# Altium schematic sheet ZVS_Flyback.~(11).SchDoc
size 431 x 279 mm; Date: Not shown in title block; ApprovedBy: Not shown in title block; CheckedBy: Not shown in title block; Author: Not shown in title block; CompanyName: Not shown in title block; Engineer: Not shown in title block; Organization: Not shown in title block; Address1: Not shown in title block; Address2: Not shown in title block; Address3: Not shown in title block; Address4: Not shown in title block; DocumentNumber: 2; Revision: Use project parameter SCH_Rev; SheetNumber: 2; SheetTotal: 2; PageSetup: Record=PageOptions¦CenterHorizontal=True¦CenterVertical=True¦PrintScale=1.00¦XCorrection=1.00¦YCorrection=1.00¦PrintKind=0¦BorderSize=5000000¦LeftOffset=0¦BottomOffset=0¦Orientation=2¦PaperLength=1000¦PaperWidth=1000¦Scale=100¦PaperSource=15¦PrintQuality=600¦MediaType=1¦DitherType=10¦PaperKind=Letter¦PrintScaleMode=1
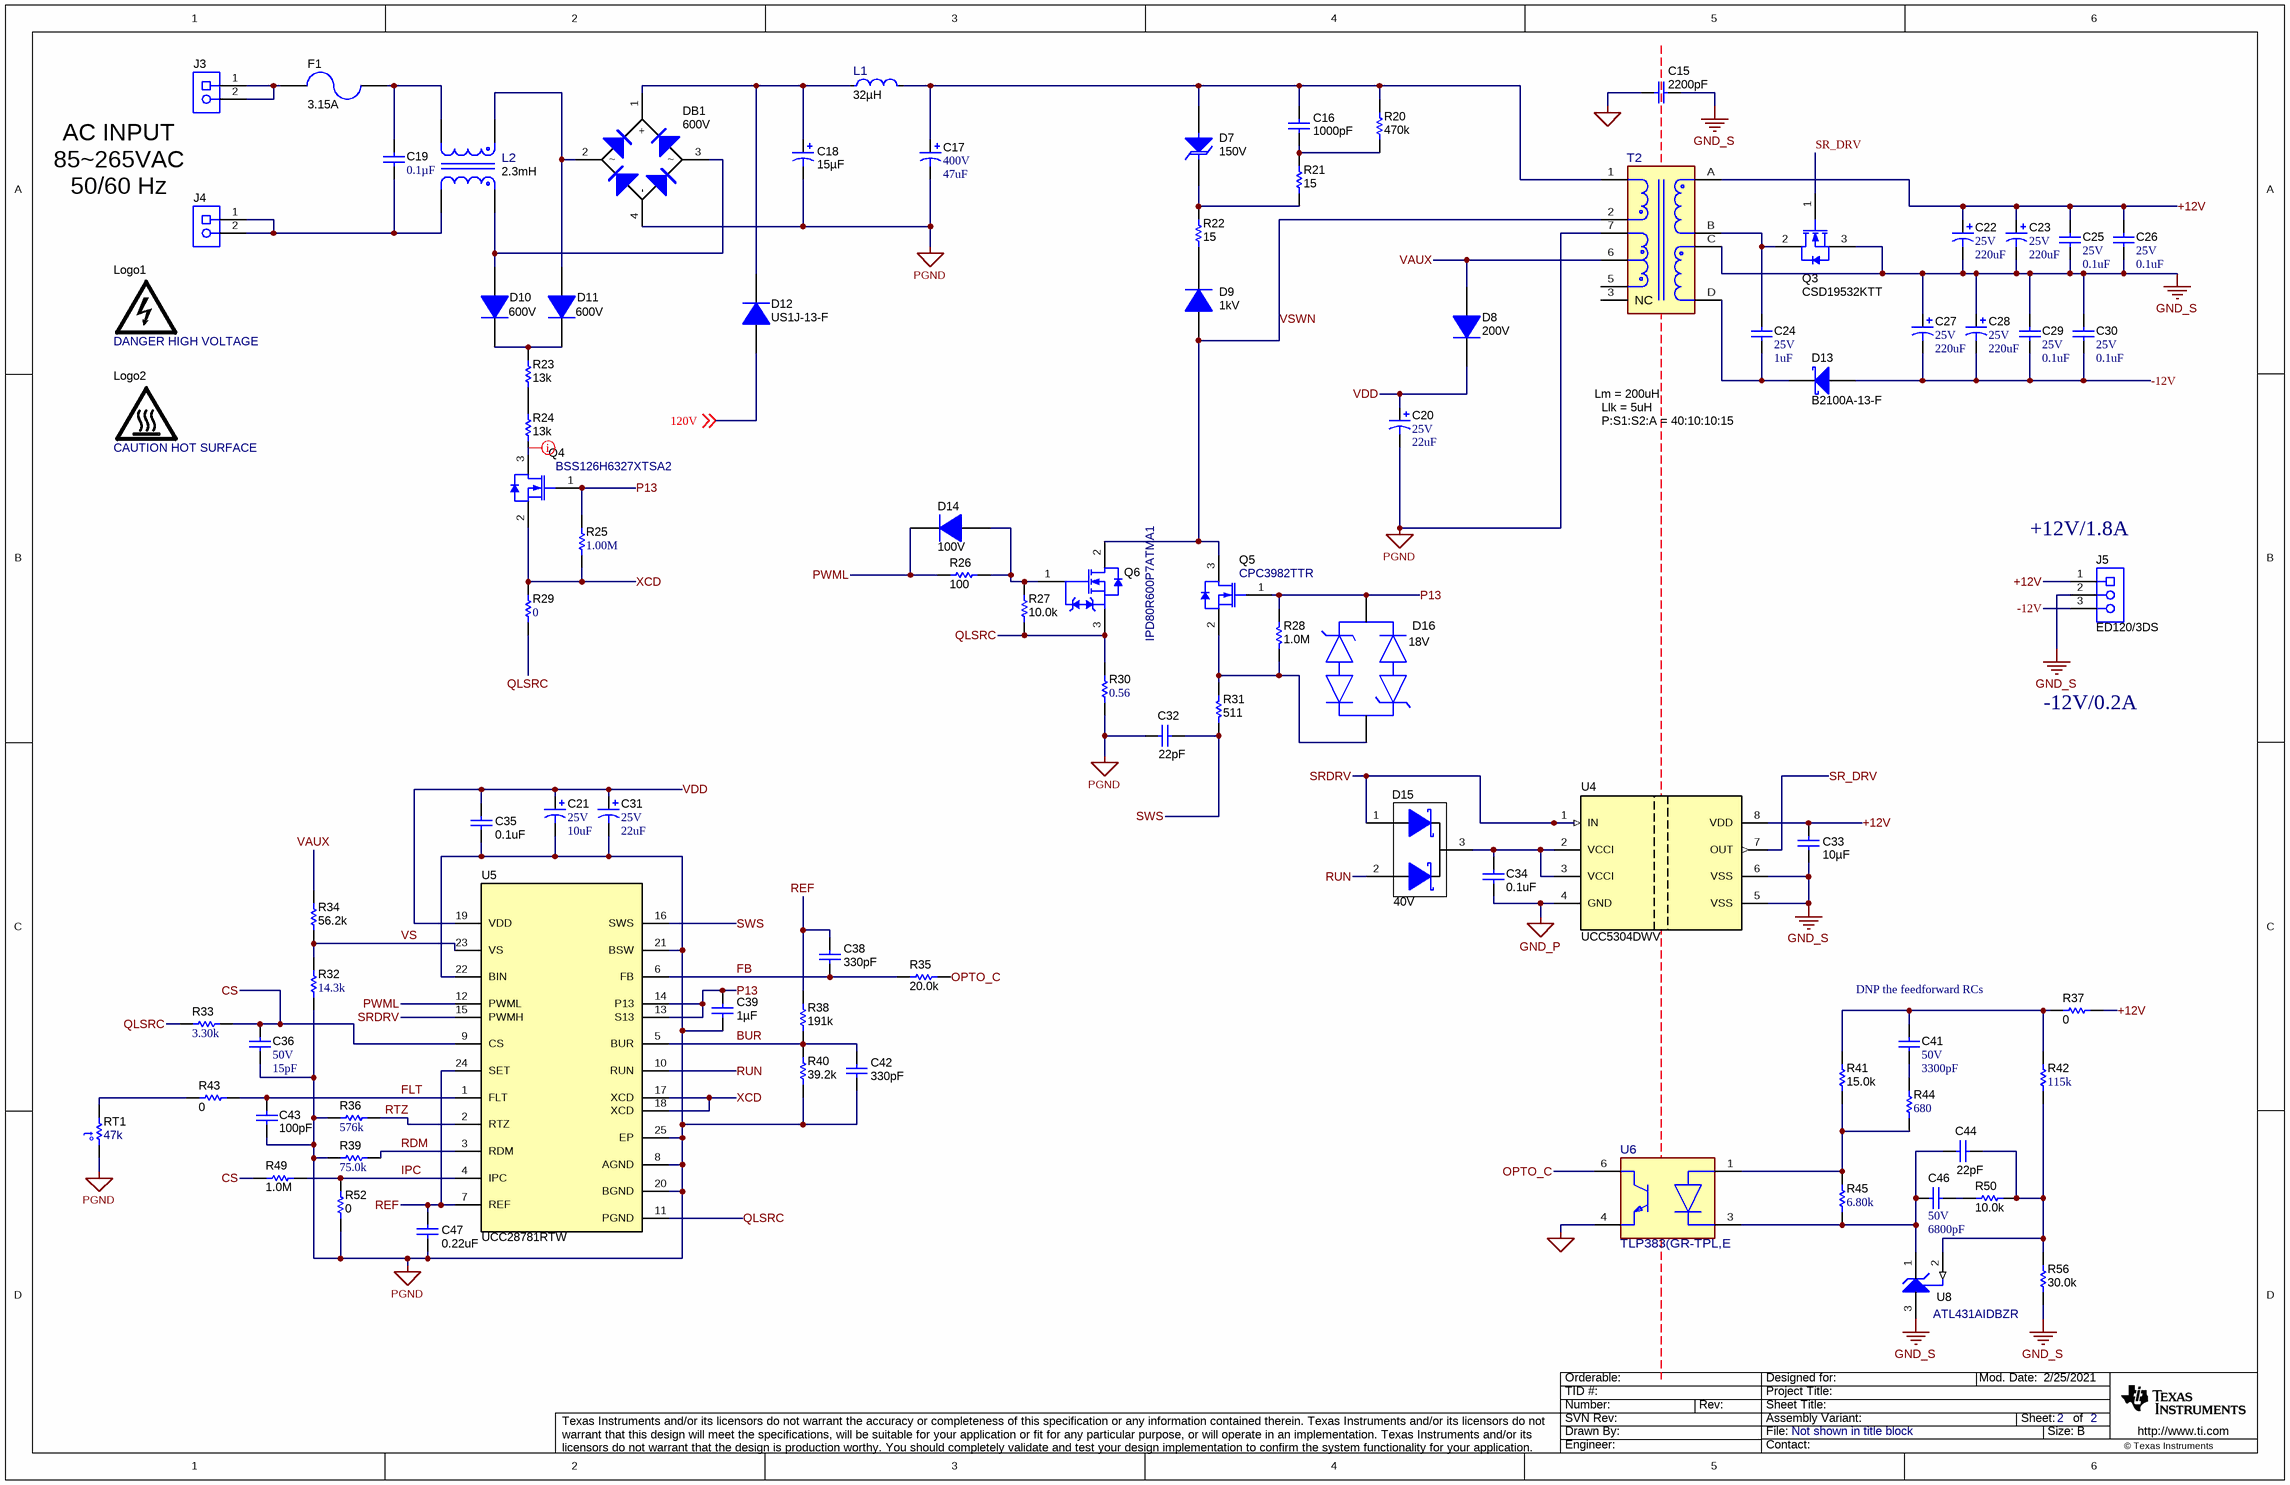
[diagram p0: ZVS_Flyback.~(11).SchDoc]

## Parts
C15  ValueDisplayed: 2200pF  [C900_9x13]  (hidden comment: C921U222MVVDBA7317)
C16  ValueDisplayed: 1000pF  [1206L]  (hidden comment: GRM31BR72J102KW01L)
C17  VDC_V: 400V  ValueDisplayed: 47uF  [CAPPR7.5-16x25]  (hidden comment: UCS2G470MHD)
C18  ValueDisplayed: 15µF  [UVC_1000x1600]  (hidden comment: UVC2G150MPD)
C19  ValueDisplayed: 0.1µF  [B32933_600x1500x2650]  (hidden comment: B32933A3104K000)
C20  VDC_V: 25V  ValueDisplayed: 22uF  [SM_RADIAL_D]  (hidden comment: EEE-FC1E220P)
C21  VDC_V: 25V  ValueDisplayed: 10uF  [CAPSMT_62_D55]  (hidden comment: EMVA250ADA100MD55G)
C22  VDC_V: 25V  ValueDisplayed: 220uF  [BT_1000x1250]  (hidden comment: UBT1E221MPD1TD)
C23  VDC_V: 25V  ValueDisplayed: 220uF  [BT_1000x1250]  (hidden comment: UBT1E221MPD1TD)
C24  VDC_V: 25V  ValueDisplayed: 1uF  [1206]  (hidden comment: GRM319R61E105KC36D)
C25  VDC_V: 25V  ValueDisplayed: 0.1uF  [0603]  (hidden comment: 06033D104KAT2A)
C26  VDC_V: 25V  ValueDisplayed: 0.1uF  [0603]  (hidden comment: 06033D104KAT2A)
C27  VDC_V: 25V  ValueDisplayed: 220uF  [BT_1000x1250]  (hidden comment: UBT1E221MPD1TD)
C28  VDC_V: 25V  ValueDisplayed: 220uF  [BT_1000x1250]  (hidden comment: UBT1E221MPD1TD)
C29  VDC_V: 25V  ValueDisplayed: 0.1uF  [0603]  (hidden comment: 06033D104KAT2A)
C30  VDC_V: 25V  ValueDisplayed: 0.1uF  [0603]  (hidden comment: 06033D104KAT2A)
C31  VDC_V: 25V  ValueDisplayed: 22uF  [SM_RADIAL_D]  (hidden comment: EEE-FC1E220P)
C32  ValueDisplayed: 22pF  [0402S]  (hidden comment: GCM1555C1H220JA16D)
C33  ValueDisplayed: 10µF  [1206_180L]  (hidden comment: C1206C106J3RACAUTO)
C34  ValueDisplayed: 0.1uF  [0402S]  (hidden comment: GRM155R71H104ME14D)
C35  ValueDisplayed: 0.1uF  [0402S]  (hidden comment: GRM155R71H104ME14D)
C36  VDC_V: 50V  ValueDisplayed: 15pF  [0402]  (hidden comment: CC0402JRNPO9BN150)
C38  ValueDisplayed: 330pF  [0402S]  (hidden comment: GRM155R71H331KA01D)
C39  Cap_F: 1µF  [0603S]  (hidden comment: CGA3E1X7R1V105K080AC)
C41  VDC_V: 50V  ValueDisplayed: 3300pF  [0402]  (hidden comment: GRM155R71H332KA01D)
C42  ValueDisplayed: 330pF  [0402S]  (hidden comment: GRM155R71H331KA01D)
C43  ValueDisplayed: 100pF  [0402S]  (hidden comment: GRM1555C1H101JA01D)
C44  ValueDisplayed: 22pF  [0402S]  (hidden comment: GCM1555C1H220JA16D)
C46  VDC_V: 50V  ValueDisplayed: 6800pF  [0402]  (hidden comment: GRM155R71H682KA88D)
C47  ValueDisplayed: 0.22uF  [0402S]  (hidden comment: GRM155R71C224KA12D)
D7  VRWM: 150V  [SMA]  (hidden comment: SMAJ150A)
D8  Vr_V: 200V  [SOD-123H]  (hidden comment: CSFMT104-HF)
D9  Vr_V: 1kV  [SMA]  (hidden comment: MRA4007T3G)
D10  Vr_V: 600V  [TUMD2SM]  (hidden comment: RFU02VSM6STR)
D11  Vr_V: 600V  [TUMD2SM]  (hidden comment: RFU02VSM6STR)
D12  US1J-13-F  [SMA]
D13  B2100A-13-F  [SMA]
D14  Vr_V: 100V  [SOD-323]  (hidden comment: BAS316,115)
D15  Vr_V: 40V  [SOT-323]  (hidden comment: BAS40W-05-7-F)
D16  CDSOD323-T18C  [FP-CDSOD323-T18C_SOD323-MFG]  (value not drawn)
DB1  value 600V  [Z4-D]  (hidden comment: Z4DGP406L-HF)
F1  Irating_A: 3.15A  [FUSE_392]  (hidden comment: 39213150000)
J3  ED120/2DS  [On-Shore_ED120_2DS]  (value not drawn)
J4  ED120/2DS  [On-Shore_ED120_2DS]  (value not drawn)
J5  ED120/3DS  [On-Shore_ED120_3DS]
L1  Ind_H: 32µH  [FP-7447052_PTH_D10MM0-MFG]  (hidden comment: 7447052)
L2  Ind_H: 2.3mH  [FP-RLTI-1387_PTH_CMC_0IN38_0IN60-MFG]  (hidden comment: RLTI-1387)
Logo1  DANGER HIGH VOLTAGE  [IEC_HighVoltage_Small]  (no BOM)
Logo2  CAUTION HOT SURFACE  [IEC_HotSurface_Small]  (no BOM)
Q3  CSD19532KTT  [KTT0002A]
Q4  BSS126H6327XTSA2  [SOT-23L]
Q5  CPC3982TTR  [SOT-23L]
Q6  IPD80R600P7ATMA1  [DPAK]
R20  ValueDisplayed: 470k  [0805_HV1]  (hidden comment: CRCW0805470KJNEA)
R21  ValueDisplayed: 15  [0805_HV1]  (hidden comment: CRCW080515R0JNEA)
R22  ValueDisplayed: 15  [0805_HV1]  (hidden comment: CRCW080515R0JNEA)
R23  ValueDisplayed: 13k  [1206L]  (hidden comment: CRCW120613K0JNEA)
R24  ValueDisplayed: 13k  [1206L]  (hidden comment: CRCW120613K0JNEA)
R25  ValueDisplayed: 1.00M  [0603]  (hidden comment: MCT06030C1004FP500)
R26  ValueDisplayed: 100  [0805_HV1]  (hidden comment: CRCW0805100RJNEA)
R27  ValueDisplayed: 10.0k  [0402S]  (hidden comment: CRCW040210K0FKED)
R28  ValueDisplayed: 1.0M  [0402S]  (hidden comment: CRCW04021M00JNED)
R29  ValueDisplayed: 0  [0603]  (hidden comment: RC0603JR-070RL)
R30  ValueDisplayed: 0.56  [1206]  (hidden comment: ERJ-8RQFR56V)
R31  ValueDisplayed: 511  [0402S]  (hidden comment: CRCW0402511RFKED)
R32  ValueDisplayed: 14.3k  [0402]  (hidden comment: CRCW040214K3FKED)
R33  ValueDisplayed: 3.30k  [0402]  (hidden comment: RK73H1ETTP3301F)
R34  ValueDisplayed: 56.2k  [0402S]  (hidden comment: CRCW040256K2FKED)
R35  ValueDisplayed: 20.0k  [0402S]  (hidden comment: CRCW040220K0FKED)
R36  ValueDisplayed: 576k  [0402]  (hidden comment: CRCW0402576KFKED)
R37  ValueDisplayed: 0  [0402S]  (hidden comment: RC0402JR-070RL)
R38  ValueDisplayed: 191k  [0402S]  (hidden comment: CRCW0402191KFKED)
R39  ValueDisplayed: 75.0k  [0402]  (hidden comment: CRCW040275K0FKED)
R40  ValueDisplayed: 39.2k  [0402S]  (hidden comment: CRCW040239K2FKED)
R41  ValueDisplayed: 15.0k  [0402S]  (hidden comment: CRCW040215K0FKED)
R42  ValueDisplayed: 115k  [0402]  (hidden comment: RC1005F1153CS)
R43  ValueDisplayed: 0  [0402S]  (hidden comment: CRCW04020000Z0EDHP)
R44  ValueDisplayed: 680  [0603]  (hidden comment: RC0603FR-07680RL)
R45  ValueDisplayed: 6.80k  [0603]  (hidden comment: RC0603FR-076K8L)
R49  ValueDisplayed: 1.0M  [0402S]  (hidden comment: CRCW04021M00JNED)
R50  ValueDisplayed: 10.0k  [0402S]  (hidden comment: CRCW040210K0FKED)
R52  ValueDisplayed: 0  [0402S]  (hidden comment: CRCW04020000Z0EDHP)
R56  ValueDisplayed: 30.0k  [0402S]  (hidden comment: CRCW040230K0FKED)
RT1  value 47k  [0603S]  (hidden comment: NCP18WB473J03RB)
T2  RLTI-1324  [FP-RLTI-1324_PTH_0IN980_0IN766-MFG]  (value not drawn)
U4  UCC5304DWV  [DWV0008A]
U5  UCC28781RTW  [RTW0024B]
U6  TLP383(GR-TPL,E  [FP-TLP383(GR-TPL,E_SO6-4-MFG]
U8  ATL431AIDBZR  [DBZ0003A_L]

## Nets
GND2: C15.2 U6.4(Emitter)
GND_P: C34.2 U4.4(GND)
GND_S: C15.1 C22.2(-) C23.2(-) C25.2 C26.2 C27.1(+) C28.1(+) C29.1 C30.1 C33.2 J5.2 Q3.3(S) R56.2 T2.C U4.5(VSS) U4.6(VSS) U8.3(ANODE)
PGND: C17.2(-) C18.2(-) C20.2(-) C21.2(-) C31.2(-) C32.1 C35.2 C36.2 C39.2 C42.2 C43.1 C47.2 DB1.4(-) R30.1 R32.1 R36.1 R39.1 R40.2 R52.1 RT1.2 T2.7 U5.8(AGND) U5.20(BGND) U5.21(BSW) U5.22(BIN) U5.25(EP)
120V: D12.2(A) ; off-sheet 120V
+12V: C22.1(+) C23.1(+) C25.1 C26.1 C33.1 J5.1 R37.1 T2.A U4.8(VDD)
-12V: C27.2(-) C28.2(-) C29.2 C30.2 D13.2(A) J5.3
BUR: C42.1 R38.2 R40.1 U5.5(BUR)
CS: C36.1 R33.2 R49.2 U5.9(CS)
FB: C38.2 R35.1 U5.6(FB)
FLT: C43.2 R43.2 U5.1(FLT)
IPC: R49.1 R52.2 U5.4(IPC)
OPTO_C: R35.2 U6.6(Collector)
P13: C39.1 D16.2 Q4.1(G) Q5.1(G) R25.2 R28.2 U5.13(S13) U5.14(P13)
PWML: D14.1(K) R26.1 U5.12(PWML)
QLSRC: Q6.3(S) R27.1 R29.1 R30.2 R33.1 U5.11(PGND)
RDM: R39.2 U5.3(RDM)
REF: C38.1 C47.1 R38.1 U5.7(REF) U5.24(SET)
RTZ: R36.2 U5.2(RTZ)
RUN: D15.2(A) U5.10(RUN)
SR_DRV: Q3.1(G) U4.7(OUT)
SRDRV: D15.1(A) U4.1(IN) U5.15(PWMH)
SWS: C32.2 R31.1 U5.16(SWS)
VAUX: D8.2(A) R34.1 T2.6
VDD: C20.1(+) C21.1(+) C31.1(+) C35.1 D8.1(K) U5.19(VDD)
VS: R32.2 R34.2 U5.23(VS)
VSWN: D9.2(A) Q5.3(D) Q6.2(D) T2.2
XCD: Q4.2(S) R25.1 R29.2 U5.17(XCD) U5.18(XCD)
NetC16_1: C16.1 C17.1(+) D7.2(A) L1.2 R20.2 T2.1
NetC16_2: C16.2 R20.1 R21.2
NetC18_1: C18.1(+) D12.1(K) DB1.1(+) L1.1
NetC19_1: C19.1 F1.1 L2.3
NetC19_2: C19.2 J4.1 J4.2 L2.2
NetC24_1: C24.1 Q3.2(D) T2.B
NetC24_2: C24.2 D13.1(K) T2.D
NetC34_1: C34.1 D15.3(K) U4.2(VCCI) U4.3(VCCI)
NetC41_1: C41.1 R37.2 R41.2 R42.2
NetC41_2: C41.2 R44.2
NetC44_1: C44.1 C46.2 R45.1 U6.3(Cathode) U8.1(CATHODE)
NetC44_2: C44.2 R42.1 R50.2 R56.1 U8.2(REF)
NetC46_1: C46.1 R50.1
NetD7_1: D7.1(K) R21.1 R22.2
NetD9_1: D9.1(K) R22.1
NetD10_1: D10.1(K) D11.1(K) R23.1
NetD10_2: D10.2(A) DB1.3 L2.1
NetD11_2: D11.2(A) DB1.2 L2.4
NetD14_2: D14.2(A) Q6.1(G) R26.2 R27.2
NetD16_1: D16.1 Q5.2(S) R28.1 R31.2
NetF1_2: F1.2 J3.1 J3.2
NetQ4_3: Q4.3(D) R24.2
NetR23_2: R23.2 R24.1
NetR41_1: R41.1 R44.1 R45.2 U6.1(Anode)
NetR43_1: R43.1 RT1.1

Not connected (* = marked no-connect by the designer): T2 3(NC) 5

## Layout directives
net class HV: NetQ4_3

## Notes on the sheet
- 85|65VAC
- AC INPUT
- 50/60 Hz
- Lm = 200uH
- Llk = 5uH
- P:S1:S2:A = 40:10:10:15
- (near J5) +12V/1.8A
- (near D16) 18V
- -12V/0.2A
- (near C41) DNP the feedforward RCs

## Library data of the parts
C15 = CMP-0078358-1: CAP, CERM, 2200 pF, X1 400 VAC/Y1 400 VAC, +/- 20%, Y5V, D9xL13mm; Manufacturer: Kemet; Cap_F: 2.2nF; SizeAreaWB_mm2: 121; VAC_X: 400V; SizeArea_mm2: 81; AEC Qualified: N; AEC Category: Q200; Value: 2200pF; TaMax_C: 125°C; SizeZ_mm: 13; TaMin_C: -40°C; SizeY_mm: 9; U/M: EA; AC_Safety: X1Y1; Cap_Case: 9x13mm
C16 = CMP-0008909-2: CAP, CERM, 1000 pF, 630 V, +/- 10%, X7R, 1206; Manufacturer: MuRata; TaMin_C: -55°C; Polarized: N; SizeAreaWB_mm2: 10.92; Value1: Unknown; U/M: EA; Value: 1000pF; TaMax_C: 125°C; SizeZ_mm: 1.35; SizeX_mm: 3.2; SizeY_mm: 1.6; Cap_Case: 1206; Value2: 630V; SizeArea_mm2: 5.12; Cap_F: 1nF; AEC Category: Q200
C17 = CMP-0010241-2: CAP, AL, 47 uF, 400 V, +/- 20%, TH; Manufacturer: Nichicon; TaMin_C: -40°C; Polarized: Y; SizeAreaWB_mm2: 324; Value1: Unknown; U/M: EA; Value: 47uF; TaMax_C: 105°C; SizeZ_mm: 25; SizeX_mm: 16; Cap_Case: Radial  16x25mm; SizeArea_mm2: 256; CompType: Capacitor; AEC Qualified: N; Cap_F: 47µF; IRMS_A: 1.18A; AEC Category: Q200
C18 = CMP-0860955-2: CAP, AL, 15 µF, 400 V, +/- 20%, AEC-Q200 Grade 2, TH; Manufacturer: Nichicon; SizeArea_mm2: 100; CompType: Capacitor; Value2: 400V; SizeZ_mm: 18; IRMS_A: 180mA; Polarized: Y; SizeX_mm: 10; Value: 15uF; TaMin_C: -40°C; AEC Grade: 2; U/M: EA; SizeAreaWB_mm2: 144; Cap_Case: 10x16; TaMax_C: 105°C; AEC Category: Q200
C19 = CMP-0077664-2: CAP, Film, 0.1 µF, X2 305 VAC, +/- 10%, AEC-Q200 Grade 2, TH; Manufacturer: TDK; TaMin_C: -40°C; Polarized: N; SizeAreaWB_mm2: 210.0; Value: 0.1uF; TaMax_C: 105°C; VAC_X: 305; SizeZ_mm: 15.0; SizeX_mm: 26.0; SizeY_mm: 5.5; SizeArea_mm2: 143.0; AEC Qualified: Y; Cap_F: 100nF; AEC Grade: 2; AEC Category: Q200
C20 C31 = CMP-0010654-1: CAP, AL, 22 uF, 25 V, +/- 20%, 1 ohm, SMD; Manufacturer: Panasonic; TaMin_C: -40°C; ESR_ohm: 1; Polarized: Y; SizeAreaWB_mm2: 84.28; Value1: 1 ohm; U/M: EA; Value: 22uF; TaMax_C: 105°C; SizeZ_mm: 5.4; SizeX_mm: 7.8; SizeY_mm: 6.6; Cap_Case: D; SizeArea_mm2: 51.48; CompType: Capacitor; Cap_F: 22µF; IRMS_A: 1.15dA; AEC Category: Q200
C21 = CMP-0010785-1: CAP, AL, 10 uF, 25 V, +/- 20%, SMD; Manufacturer: Chemi-Con; TaMin_C: -40°C; Polarized: Y; SizeAreaWB_mm2: 28.09; Value1: Unknown; U/M: EA; Value: 10uF; TaMax_C: 85°C; SizeZ_mm: 5.2; SizeX_mm: 4.3; Cap_Case: D55; SizeArea_mm2: 18.49; CompType: Capacitor; Cap_F: 10µF; IRMS_A: 24mA; AEC Category: Q200
C22 C23 C27 C28 = CMP-0010527-1: CAP, AL, 220 uF, 25 V, +/- 20%, 0.1 ohm, TH; Manufacturer: Nichicon; TaMin_C: -40°C; ESR_ohm: 1d; Polarized: Y; SizeAreaWB_mm2: 144; Value1: 0.1 ohm; U/M: EA; Value: 220uF; TaMax_C: 125°C; SizeZ_mm: 14.5; SizeX_mm: 10; Cap_Case: 10x12.5mm; SizeArea_mm2: 100; CompType: Capacitor; Cap_F: 220µF; IRMS_A: 6.8dA; AEC Category: Q200
C24 = CMP-0008863-2: CAP, CERM, 1 uF, 25 V, +/- 10%, X5R, 1206; Manufacturer: MuRata; TaMin_C: -55°C; ESR_ohm: 0.01; Polarized: N; SizeAreaWB_mm2: 10.92; Value1: 0.01 ohm; U/M: EA; Value: 1uF; TaMax_C: 85°C; SizeZ_mm: 1.35; SizeX_mm: 3.2; SizeY_mm: 1.6; SizeArea_mm2: 5.12; Cap_F: 1µF; AEC Category: Q200
C25 C26 C29 C30 = CMP-0006758-5: CAP, CERM, 0.1 uF, 25 V, +/- 10%, X5R, 0603; Manufacturer: AVX; TaMin_C: -55°C; ESR_ohm: 0.048; Polarized: N; SizeAreaWB_mm2: 4.68; Value1: 0.048 ohm; U/M: EA; Value: 0.1uF; TaMax_C: 85°C; SizeZ_mm: 1; SizeX_mm: 1.6; SizeY_mm: 0.8; SizeArea_mm2: 1.28; Cap_F: 100nF; IRMS_A: 5.3dA; AEC Category: Q200
C32 C44 = CMP-0006348-2: CAP, CERM, 22 pF, 50 V, +/- 5%, C0G/NP0, AEC-Q200 Grade 1, 0402; Manufacturer: MuRata; TaMin_C: -55°C; Polarized: N; SizeAreaWB_mm2: 3; Value1: Unknown; U/M: EA; Value: 22pF; TaMax_C: 125°C; SizeZ_mm: 0.6; SizeX_mm: 1; SizeY_mm: 0.5; Cap_Case: 0402; Value2: 50V; AEC Qualified: Y; AEC Category: Q200
C33 = CMP-0081062-1: CAP, CERM, 10 µF, 25 V,+/- 5%, X7R, AEC-Q200 Grade 1, 1206; Manufacturer: Kemet; TaMin_C: -55°C; Polarized: N; SizeAreaWB_mm2: 10.92; U/M: EA; Value: 10uF; TaMax_C: 125°C; SizeZ_mm: 1.8; SizeX_mm: 3.2; SizeY_mm: 1.6; Cap_Case: 1206_180; Value2: 25V; SizeArea_mm2: 5.12; AEC Qualified: Y; AEC Grade: 1; AEC Category: Q200
C34 C35 = CMP-0006675-2: CAP, CERM, 0.1 uF, 50 V, +/- 20%, X7R, 0402; Manufacturer: MuRata; TaMin_C: -55°C; Polarized: N; SizeAreaWB_mm2: 3; Value1: Unknown; U/M: EA; Value: 0.1uF; TaMax_C: 125°C; SizeZ_mm: 0.6; SizeX_mm: 1; SizeY_mm: 0.5; Cap_Case: 0402; Value2: 50V; Cap_F: 100nF; AEC Category: Q200
C36 = CMP-0006304-2: CAP, CERM, 15 pF, 50 V, +/- 5%, C0G/NP0, 0402; Manufacturer: Yageo America; TaMin_C: -55°C; Polarized: N; SizeAreaWB_mm2: 3; Value1: Unknown; U/M: EA; Value: 15pF; TaMax_C: 125°C; SizeZ_mm: 0.6; SizeX_mm: 1; SizeY_mm: 0.5; AEC Category: Q200
C38 C42 = CMP-0006687-2: CAP, CERM, 330 pF, 50 V, +/- 10%, X7R, 0402; Manufacturer: MuRata; TaMin_C: -55°C; Polarized: N; SizeAreaWB_mm2: 3; Value1: Unknown; U/M: EA; Value: 330pF; TaMax_C: 125°C; SizeZ_mm: 0.6; SizeX_mm: 1; SizeY_mm: 0.5; Cap_Case: 0402; Value2: 50V; AEC Category: Q200
C39 = CMP-0007067-4: CAP, CERM, 1 uF, 35 V, +/- 10%, X7R, AEC-Q200 Grade 1, 0603; Manufacturer: TDK; TaMin_C: -55°C; ESR_ohm: 5.522m; Polarized: N; SizeAreaWB_mm2: 4.68; Value1: 0.005522 ohm; U/M: EA; Value: 1uF; TaMax_C: 125°C; SizeZ_mm: 1; SizeX_mm: 1.6; SizeY_mm: 0.8; Cap_Case: 0603; Value2: 35V; SizeArea_mm2: 1.28; AEC Qualified: Y; IRMS_A: 2.21617A; AEC Category: Q200
C41 = CMP-0006688-2: CAP, CERM, 3300 pF, 50 V, +/- 10%, X7R, 0402; Manufacturer: MuRata; TaMin_C: -55°C; Polarized: N; SizeAreaWB_mm2: 3; Value1: Unknown; U/M: EA; Value: 3300pF; TaMax_C: 125°C; SizeZ_mm: 0.6; SizeX_mm: 1; SizeY_mm: 0.5; Cap_F: 3.3nF; AEC Category: Q200
C43 = CMP-0006410-2: CAP, CERM, 100 pF, 50 V, +/- 5%, C0G/NP0, 0402; Manufacturer: MuRata; TaMin_C: -55°C; Polarized: N; SizeAreaWB_mm2: 3; Value1: Unknown; U/M: EA; Value: 100pF; TaMax_C: 125°C; SizeZ_mm: 0.6; SizeX_mm: 1; SizeY_mm: 0.5; Cap_Case: 0402; Value2: 50V; AEC Category: Q200
C46 = CMP-0006696-2: CAP, CERM, 6800 pF, 50 V, +/- 10%, X7R, 0402; Manufacturer: MuRata; TaMin_C: -55°C; Polarized: N; SizeAreaWB_mm2: 3; Value1: Unknown; U/M: EA; Value: 6800pF; TaMax_C: 125°C; SizeZ_mm: 0.6; SizeX_mm: 1; SizeY_mm: 0.5; Cap_F: 6.8nF; AEC Category: Q200
C47 = CMP-0006648-2: CAP, CERM, 0.22 uF, 16 V, +/- 10%, X7R, 0402; Manufacturer: MuRata; TaMin_C: -55°C; Polarized: N; SizeAreaWB_mm2: 3; Value1: Unknown; U/M: EA; Value: 0.22uF; TaMax_C: 125°C; SizeZ_mm: 0.6; SizeX_mm: 1; SizeY_mm: 0.5; Cap_Case: 0402; Value2: 16V; Cap_F: 220nF; AEC Category: Q200
D7 = CMP-0084982-1: Diode, TVS, Uni, 150 V, 243 Vc, 400 W, 1.6 A, SMA; Manufacturer: Littelfuse; Vc: 243V; Ipp: 1.6A; RJA_CperW: 120; AEC Qualified: N; Value: 150V; Ppk: 400W; AEC Category: Q101; SizeArea_mm2: 16.3228; SizeAreaWB_mm2: 37.3428; SizeZ_mm: 2.87; Vbr_Max: 185V; SizeX_mm: 5.59; SizeY_mm: 2.92; Vbr_Min: 167V
D8 = CMP-0029199-2: Diode, Superfast Rectifier, 200 V, 1 A, 3.5x1.6mm; Manufacturer: Comchip Technology; Vf_V: 950mV; Value: 200V; Value1: 1A; Value2: 0.95V; TJmax_C: 150°C; SizeAreaWB_mm2: 11.7; SizeArea_mm2: 5.6; SizeX_mm: 3.5; SizeY_mm: 1.6; SizeZ_mm: 1; AEC Category: Q101; AEC Qualified: N
D9 = CMP-0077082-2: Diode, Standard Recovery Rectifier, 1000 V, 1 A, AEC-Q101, SMA; Manufacturer: ON Semiconductor; SizeAreaWB_mm2: 37.3428; SizeArea_mm2: 16.3228; AEC Qualified: Y; TJmax_C: 175°C; AEC Category: Q101; Value: 1000V; SizeZ_mm: 2.87; Green_REACh: Passed; Io_A: 1A; Vf_V: 1.1V; SizeY_mm: 2.92; Green_Lifecycle: Active; SizeX_mm: 5.59; RJC_CperW: 16.2
D10 D11 = CMP-0080762-2: Diode, Standard Recovery Rectifier, 600 V, 0.2 A, 2x1.4mm; Manufacturer: Rohm; SizeArea_mm2: 3.5; AEC Qualified: N; SizeY_mm: 1.4; Io_A: 200mA; SizeZ_mm: 0.8; Vf_V: 2.2V; SizeAreaWB_mm2: 8.4; TJmax_C: 150°C; Value1: 0.2A; SizeX_mm: 2.5; AEC Category: Q101; Value: 600V
D12 = CMP-0077027-2: Diode, Ultrafast, 600 V, 1 A, SMA; Manufacturer: Diodes Inc.; Value: 600V; TJmax_C: 150°C; Value1: 1A; Value2: 1.7V; SizeY_mm: 2.92; Green_REACh: Passed; Green_Lifecycle: Active; SizeX_mm: 5.59; AEC Category: Q101; SizeAreaWB_mm2: 37.3428; SizeZ_mm: 2.87; SizeArea_mm2: 16.3228
D13 = CMP-0081099-2: Diode, Schottky, 100 V, 2 A, SMA; Manufacturer: Diodes Inc.; SizeZ_mm: 2.87; SizeX_mm: 5.59; AEC Qualified: N; Value2: 0.79V; SizeArea_mm2: 16.3228; Vf_V: 790mV; AEC Category: Q101; TJmax_C: 125°C; Vr_V: 100V; Value: 100V; Io_A: 2A; SizeAreaWB_mm2: 37.3428; SizeY_mm: 2.92
D14 = CMP-0029006-2: Diode, Ultrafast, 100 V, 0.25 A, SOD-323; Manufacturer: Nexperia; SizeY_mm: 1.35; Value1: 0.25A; SizeAreaWB_mm2: 8.695; SizeZ_mm: 1; Io_A: 250mA; Value2: 1.4V; SizeX_mm: 2.7; Green_REACh: Incomplete; TJmax_C: 150°C; Green_Lifecycle: Not Set; AEC Category: Q101; Value: 100V; SizeArea_mm2: 3.645
D15 = CMP-0028437-2: Diode, Schottky, 40 V, 0.2 A, SOT-323; Manufacturer: Diodes Inc.; Io_A: 200mA; Green_Lifecycle: Not Set; SizeAreaWB_mm2: 10.24; Green_REACh: Incomplete; Value1: 0.2A; Value: 40V; SizeZ_mm: 1.1; SizeX_mm: 2.2; Vf_V: 800mV; Value2: 0.8V; SizeArea_mm2: 4.84; AEC Category: Q101
D16 = CMP-0087587-1: Diode, TVS, Bi, 18 V, SOD-323; Manufacturer: Bourns Inc.; SizeZ_mm: 1.14mm; AEC Qualified: No
DB1 = Z4DGP406L-HF: Diode, P-N-Bridge, 600 V, 4 A, Z4-D; Manufacturer: Comchip Technology; U/M: EA; Vf_V: 0.95; Value1: 4A; Value2: 0.95V; Io_A: 4; Vr_V: 600; TJmax_C: 175; SizeAreaWB_mm2: 126.25; SizeArea_mm2: 85.05; SizeX_mm: 10.5; SizeY_mm: 8.1; SizeZ_mm: 1.55; AEC Category: Q101; AEC Qualified: N; Green_Lifecycle: Not Set; Green_REACh: Incomplete
F1 = CMP-0003561-2: Fuse, 3.15 A, 250VAC/VDC, TH; Manufacturer: Littelfuse; VAC_V: 250V
J3 J4 = CMP-0074910-1: Terminal Block, 5.08 mm, 2x1, Brass, TH; Manufacturer: On-Shore Technology; Pitch_mm: 5.08; Gender: Female; Shrouded: N; Row_Count: 1; Current_A: 15A; Voltage_V: 300V; Cert_CULUS: Y; CNHeader: False; CT: True; Green_Lifecycle: Not Set; Green_REACh: Incomplete
J5 = CMP-0074911-1: Terminal Block, 5.08 mm, 3x1, Brass, TH; Manufacturer: On-Shore Technology; Cert_VDE: Y; CNHeader: False; Current_A: 15A; Green_Lifecycle: Not Set; Shrouded: N; Gender: Female; Green_REACh: Incomplete; Voltage_V: 300V; Row_Count: 1; Pitch_mm: 5.08; CT: True
L1 = CMP-0087546-1: WE-FI Leaded Toroidal Line Choke; Manufacturer: Wurth; SizeZ_mm: 10mm; Irms: 2.6A; DCR_ohm: 0.045; AEC Qualified: No; Symbol Name: SYM-7447052
L2 = CMP-0092946-1: Common Mode Choke, 2.3mH 35%, 0.6x0.38x0.75 IN; Manufacturer: Renco; Test Frequency: 10kHz; SizeZ_mm: 0.75inch; DCR_ohm: 0.03; AEC Qualified: No
Logo1 = CMP-0074835-1: IEC 61010-1 High Voltage Warning; SymbolCreator: a0412235
Logo2 = CMP-0074837-1: IEC 61010-1 Hot Surface Warning; SymbolCreator: a0412235
Q3 = CMP-0000957-3: MOSFET, N-CH, 100 V, 136 A, KTT0002A (TO-263-2); Alternate Manufacturer: None; Manufacturer: Texas Instruments; SizeZ_mm: 4.7; ChType: N; Value2: 44 nC; VdsMax_V: 100V; SizeX_mm: 14.3; SizeAreaWB_mm2: 198.208; SizeY_mm: 10.16; Vgs_V: 20V; QgTyp_nC: 44; Value: 100V; SizeArea_mm2: 145.288; AEC Category: Q101; IdsMax_A: 136A
Q4 = CMP-0067574-2: MOSFET, N-CH, Depletion Mode, 100 V, 0.17 A, AEC-Q101, SOT-23; Manufacturer: Infineon Technologies; Alternate Manufacturer: None; ChType: N; Value: 600V; Value1: ? ohm; Value2: 1.4 nC; QgTyp_nC: 1.4; Vgs_V: 20V; IdsMax_A: 21mA; SizeAreaWB_mm2: 14.0; SizeArea_mm2: 7.5; SizeX_mm: 2.5; SizeY_mm: 3.0; SizeZ_mm: 1.1; AEC Category: Q101; AEC Qualified: Y
Q5 = CMP-0081263-2: MOSFET, N-CH, Depletion Mode, 800 V, SOT-23; Alternate Manufacturer: None; Manufacturer: IXYS; SizeAreaWB_mm2: 14; Vgs_V: 15V; Value1: ? ohm; VdsMax_V: 800V; Value: 800V; SizeZ_mm: 1.1; SizeX_mm: 2.5; SizeY_mm: 3; Value2: ? nC; SizeArea_mm2: 7.5; ChType: N; AEC Category: Q101
Q6 = CMP-0083711-2: MOSFET, N-CH, 800 V, 8 A, DPAK; Manufacturer: Infineon Technologies; Alternate Manufacturer: None; AEC Qualified: N; Vgs_V: 20V; SizeY_mm: 6.54; VdsMax_V: 800V; IdsMax_A: 8A; SizeX_mm: 9.91; Value2: 20 nC; AEC Category: Q101; ChMode: Enhancement; SizeAreaWB_mm2: 101.7114; Value1: ? ohm; SizeArea_mm2: 64.8114; Value: 800V; SizeZ_mm: 2.29; QgTyp_nC: 20
R20 = CMP-0020554-3: RES, 470 k, 5%, 0.125 W, AEC-Q200 Grade 0, 0805; Manufacturer: Vishay-Dale; Power_W: 125mW; TempCo: 200 ppm/C; Value: 470k; EIA_Code: E24; SizeX_mm: 2; SizeY_mm: 1.25; SizeZ_mm: 1.45; Value2: 0.125W; SizeArea_mm2: 2.5; AEC Qualified: Y; VDC_V: 150V; AEC Category: Q200; AEC Grade: 0
R21 R22 = CMP-0020464-3: RES, 15, 5%, 0.125 W, AEC-Q200 Grade 0, 0805; Manufacturer: Vishay-Dale; Power_W: 125mW; TempCo: 200 ppm/C; Value_Code: 15R0; Value: 15; EIA_Code: E24; SizeX_mm: 2; SizeY_mm: 1.25; SizeZ_mm: 1.45; Value2: 0.125W; SizeArea_mm2: 2.5; AEC Qualified: Y; VDC_V: 150V; AEC Category: Q200; AEC Grade: 0
R23 R24 = CMP-0018589-3: RES, 13 k, 5%, 0.25 W, AEC-Q200 Grade 0, 1206; Manufacturer: Vishay-Dale; Power_W: 250mW; TempCo: 200 ppm/C; Value_Code: 13k0; Value: 13k; EIA_Code: E24; SizeX_mm: 3.2; SizeY_mm: 1.6; SizeZ_mm: 1.35; Value2: 0.25W; SizeArea_mm2: 5.12; AEC Qualified: Y; VDC_V: 200V; AEC Category: Q200; AEC Grade: 0
R25 = CMP-0022731-2: RES, 1.00 M, 1%, 0.125 W, 0603; Manufacturer: Vishay/Beyschlag; Power_W: 125mW; TempCo: 50 ppm/C; Value_Code: 1M00; U/M: EA; Value: 1.00Meg; EIA_Code: E96; Res_ohm: 1M; SizeX_mm: 1.6; SizeY_mm: 0.8; SizeZ_mm: 1; Value2: 0.125W; SizeArea_mm2: 1.28; AEC Qualified: N; VDC_V: 75V; AEC Category: Q200
R26 = CMP-0020445-3: RES, 100, 5%, 0.125 W, AEC-Q200 Grade 0, 0805; Manufacturer: Vishay-Dale; Power_W: 125mW; TempCo: 200 ppm/C; Value_Code: 100R; Value: 100; EIA_Code: E24; SizeX_mm: 2; SizeY_mm: 1.25; SizeZ_mm: 1.45; Value2: 0.125W; SizeArea_mm2: 2.5; AEC Qualified: Y; VDC_V: 150V; AEC Category: Q200; AEC Grade: 0
R27 R50 = CMP-0025958-3: RES, 10.0 k, 1%, 0.063 W, AEC-Q200 Grade 0, 0402; Manufacturer: Vishay-Dale; Power_W: 63mW; TempCo: 100 ppm/C; Value_Code: 10k0; Value: 10.0k; EIA_Code: E96; Res_ohm: 10k; SizeX_mm: 1; SizeY_mm: 0.5; SizeZ_mm: 0.6; Value2: 0.063W; AEC Qualified: Y; VDC_V: 50V; AEC Category: Q200; AEC Grade: 0
R28 = CMP-0026859-2: RES, 1.0 M, 5%, 0.063 W, AEC-Q200 Grade 0, 0402; Manufacturer: Vishay-Dale; Value: 1.0Meg; Res_ohm: 1M; Value_Code: 1M00; Power_W: 63mW; Value2: 0.063W; VDC_V: 50V; TempCo: 200 ppm/C; SizeArea_mm2: 0.5; SizeX_mm: 1; SizeZ_mm: 0.6; EIA_Code: E24; AEC Category: Q200; AEC Qualified: Y; AEC Grade: 0
R29 = CMP-0025885-5: RES, 0, 5%, 0.1 W, 0603; Manufacturer: Yageo; Power_W: 100mW; TempCo: 200 ppm/C; Value_Code: 0000; Value: 0; EIA_Code: E24; SizeX_mm: 1.6; SizeZ_mm: 1; Value2: 0.1W; SizeArea_mm2: 1.28; AEC Qualified: N; VDC_V: 75V; AEC Category: Q200; SizeY_mm: 0.8; SizeAreaWB_mm2: 4.68
R30 = CMP-0017792-3: RES, 0.56, 1%, 0.25 W, AEC-Q200 Grade 0, 1206; Manufacturer: Panasonic; Power_W: 250mW; TempCo: 250 ppm/C; Value_Code: R560; Value: 0.56; EIA_Code: E96; SizeX_mm: 3.2; SizeY_mm: 1.6; SizeZ_mm: 1.35; Value2: 0.25W; SizeArea_mm2: 5.12; AEC Qualified: Y; AEC Category: Q200; AEC Grade: 0; SizeAreaWB_mm2: 10.92
R31 = CMP-0026436-2: RES, 511, 1%, 0.063 W, AEC-Q200 Grade 0, 0402; Manufacturer: Vishay-Dale; Power_W: 63mW; TempCo: 100 ppm/C; Value_Code: 511R; Value: 511; EIA_Code: E96; SizeX_mm: 1; SizeY_mm: 0.5; SizeZ_mm: 0.6; Value2: 0.063W; AEC Qualified: Y; VDC_V: 50V; AEC Category: Q200; AEC Grade: 0
R32 = CMP-0026016-3: RES, 14.3 k, 1%, 0.063 W, AEC-Q200 Grade 0, 0402; Manufacturer: Vishay-Dale; Power_W: 63mW; TempCo: 100 ppm/C; Value_Code: 14k3; Value: 14.3k; EIA_Code: E96; SizeX_mm: 1; SizeY_mm: 0.5; SizeZ_mm: 0.6; Value2: 0.063W; AEC Qualified: Y; VDC_V: 50V; AEC Category: Q200; AEC Grade: 0
R33 = CMP-0026750-1: RES, 3.30 k, 1%, 0.063 W, AEC-Q200 Grade 0, 0402; Manufacturer: KOA Speer; Power_W: 63mW; TempCo: 100 ppm/C; Value_Code: 3k30; U/M: EA; Value: 3.30k; Res_ohm: 3.3k; SizeX_mm: 1; SizeY_mm: 0.5; SizeZ_mm: 0.6; Value2: 0.063W; AEC Qualified: Y; VDC_V: 50V; AEC Grade: 0; AEC Category: Q200
R34 = CMP-0026453-2: RES, 56.2 k, 1%, 0.063 W, AEC-Q200 Grade 0, 0402; Manufacturer: Vishay-Dale; Power_W: 63mW; TempCo: 100 ppm/C; Value_Code: 56k2; Value: 56.2k; EIA_Code: E96; SizeX_mm: 1; SizeY_mm: 0.5; SizeZ_mm: 0.6; Value2: 0.063W; AEC Qualified: Y; VDC_V: 50V; AEC Category: Q200; AEC Grade: 0
R35 = CMP-0026162-2: RES, 20.0 k, 1%, 0.063 W, AEC-Q200 Grade 0, 0402; Manufacturer: Vishay-Dale; Power_W: 63mW; TempCo: 100 ppm/C; Value_Code: 20k0; Value: 20.0k; EIA_Code: E96; Res_ohm: 20k; SizeX_mm: 1; SizeY_mm: 0.5; SizeZ_mm: 0.6; Value2: 0.063W; AEC Qualified: Y; VDC_V: 50V; AEC Category: Q200; AEC Grade: 0
R36 = CMP-0026455-2: RES, 576 k, 1%, 0.063 W, AEC-Q200 Grade 0, 0402; Manufacturer: Vishay-Dale; Power_W: 63mW; TempCo: 100 ppm/C; Value: 576k; EIA_Code: E96; SizeX_mm: 1; SizeY_mm: 0.5; SizeZ_mm: 0.6; Value2: 0.063W; AEC Qualified: Y; VDC_V: 50V; AEC Category: Q200; AEC Grade: 0
R37 = CMP-0027004-2: RES, 0, 5%, 0.063 W, 0402; Manufacturer: Yageo America; Power_W: 63mW; TempCo: 200 ppm/C; Value_Code: 0000; U/M: EA; Value: 0; EIA_Code: E24; SizeX_mm: 1; SizeY_mm: 0.5; SizeZ_mm: 0.6; Value2: 0.063W; VDC_V: 50V; AEC Category: Q200
R38 = CMP-0026063-3: RES, 191 k, 1%, 0.063 W, AEC-Q200 Grade 0, 0402; Manufacturer: Vishay-Dale; Power_W: 63mW; TempCo: 100 ppm/C; Value: 191k; EIA_Code: E96; SizeX_mm: 1; SizeY_mm: 0.5; SizeZ_mm: 0.6; Value2: 0.063W; AEC Qualified: Y; VDC_V: 50V; AEC Category: Q200; AEC Grade: 0
R39 = CMP-0026543-2: RES, 75.0 k, 1%, 0.063 W, AEC-Q200 Grade 0, 0402; Manufacturer: Vishay-Dale; Power_W: 63mW; TempCo: 100 ppm/C; Value_Code: 75k0; Value: 75.0k; EIA_Code: E96; Res_ohm: 75k; SizeX_mm: 1; SizeY_mm: 0.5; SizeZ_mm: 0.6; Value2: 0.063W; AEC Qualified: Y; VDC_V: 50V; AEC Category: Q200; AEC Grade: 0
R40 = CMP-0026327-2: RES, 39.2 k, 1%, 0.063 W, AEC-Q200 Grade 0, 0402; Manufacturer: Vishay-Dale; Power_W: 63mW; TempCo: 100 ppm/C; Value_Code: 39k2; Value: 39.2k; EIA_Code: E96; SizeX_mm: 1; SizeY_mm: 0.5; SizeZ_mm: 0.6; Value2: 0.063W; AEC Qualified: Y; VDC_V: 50V; AEC Category: Q200; AEC Grade: 0
R41 = CMP-0026027-3: RES, 15.0 k, 1%, 0.063 W, AEC-Q200 Grade 0, 0402; Manufacturer: Vishay-Dale; Power_W: 63mW; TempCo: 100 ppm/C; Value_Code: 15k0; Value: 15.0k; EIA_Code: E96; Res_ohm: 15k; SizeX_mm: 1; SizeY_mm: 0.5; SizeZ_mm: 0.6; Value2: 0.063W; AEC Qualified: Y; VDC_V: 50V; AEC Category: Q200; AEC Grade: 0
R42 = CMP-0077547-1: RES, 115 k, 1%, 0.0625 W, 0402; Manufacturer: Samsung Electro-Mechanics; Power_W: 62.5mW; TempCo: 300 ppm/C; U/M: EA; Value: 115k; EIA_Code: E96; SizeX_mm: 1.0; SizeY_mm: 0.5; SizeZ_mm: 0.6; AEC Qualified: N; VDC_V: 50V; AEC Category: Q200
R43 R52 = CMP-0081856-1: RES, 0, 0%, 0.2 W, AEC-Q200 Grade 0, 0402; Manufacturer: Vishay-Dale; SizeAreaWB_mm2: 3; SizeArea_mm2: 0.5; AEC Qualified: Y; AEC Category: Q200; Value: 0; SizeZ_mm: 0.6; Power_W: 200mW; VDC_V: 50V; Value2: 0.2W; SizeX_mm: 1
R44 = CMP-0023235-5: RES, 680, 1%, 0.1 W, 0603; Manufacturer: Yageo; Power_W: 100mW; TempCo: 100 ppm/C; Value_Code: 680R; Value: 680; SizeX_mm: 1.6; SizeY_mm: 0.8; SizeZ_mm: 1; Value2: 0.1W; SizeArea_mm2: 1.28; AEC Qualified: N; VDC_V: 75V; AEC Category: Q200; SizeAreaWB_mm2: 4.68
R45 = CMP-0023253-5: RES, 6.80 k, 1%, 0.1 W, 0603; Manufacturer: Yageo; Power_W: 100mW; TempCo: 100 ppm/C; Value_Code: 6k80; Value: 6.80k; Res_ohm: 6.8k; SizeX_mm: 1.6; SizeY_mm: 0.8; SizeZ_mm: 1; Value2: 0.1W; SizeArea_mm2: 1.28; AEC Qualified: N; VDC_V: 75V; AEC Category: Q200; SizeAreaWB_mm2: 4.68
R49 = CMP-0026859-2: RES, 1.0 M, 5%, 0.063 W, AEC-Q200 Grade 0, 0402; Manufacturer: Vishay-Dale; Power_W: 63mW; TempCo: 200 ppm/C; Value_Code: 1M00; Value: 1.0Meg; EIA_Code: E24; Res_ohm: 1M; SizeX_mm: 1; SizeY_mm: 0.5; SizeZ_mm: 0.6; Value2: 0.063W; AEC Qualified: Y; VDC_V: 50V; AEC Category: Q200; AEC Grade: 0
R56 = CMP-0078244-2: RES, 30.0 k, 1%, 0.063 W, AEC-Q200 Grade 0, 0402; Manufacturer: Vishay-Dale; Power_W: 63mW; Green_Lifecycle: Active; TempCo: 100 ppm/C; Value_Code: 30k0; Green_REACh: Passed; Value: 30.0k; Res_ohm: 30k; SizeX_mm: 1; SizeY_mm: 0.5; SizeZ_mm: 0.6; Value2: 0.063W; AEC Qualified: Y; VDC_V: 50V; AEC Grade: 0; AEC Category: Q200
RT1 = CMP-0002523-3: Thermistor NTC, 47k ohm, 5%, 0603; Manufacturer: MuRata; TaMax_C: 125°C; SizeX_mm: 1.6; SizeY_mm: 0.8; TaMin_C: -40°C; Power_W: 100mW; SizeZ_mm: 1; SizeArea_mm2: 1.28; SizeAreaWB_mm2: 4.68; U/M: EA
T2 = CMP-0087465-1: Lm=200uH, Llk=5uH / P:S1:S2:A = 40:10:10:15; Manufacturer: Renco Electronics; AEC Qualified: No; SizeZ_mm: 0.66inch; DCR_ohm: 0.1; Ind_H: 110µH; Ns1toNp: 2.5:0.5:1:0.5:1
U4 = CMP-0860377-2: 4-A/6-A, Single-Channel Reinforced Isolation Gate Driver with High Noise Immunity, DWV0008A (SOIC-8); Manufacturer: Texas Instruments; SizeX_mm: 11.5; SizeArea_mm2: 67.275; SizeAreaWB_mm2: 105.975; CompType: IC; SizeZ_mm: 2.8; SizeY_mm: 5.85; AEC Category: Q200; AEC Qualified: N
U5 = CMP-0086087-1: UCC28781RTW, RTW0024B (WQFN-24); Manufacturer: Texas Instruments; SizeY_mm: 4; SizeZ_mm: 0.8; AEC Category: Q200; SizeArea_mm2: 16; CompType: IC; AEC Qualified: N; SizeAreaWB_mm2: 25
U6 = CMP-0087394-2: Optoisolator Transistor Output 5000Vrms 1 Channel 6-SO; Manufacturer: Toshiba; CTR (Max): 300%; CTR (Min): 100%; SizeZ_mm: 2.3mm
U8 = CMP-0066199-1: 2.5V Low Iq Adjustable Precision Shunt Regulator, DBZ0003A (SOT-23-3); Manufacturer: Texas Instruments; SizeArea_mm2: 7.5; SizeAreaWB_mm2: 14.0; SizeX_mm: 2.5; SizeY_mm: 3.0; SizeZ_mm: 1.12; CompType: IC; U/M: EA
